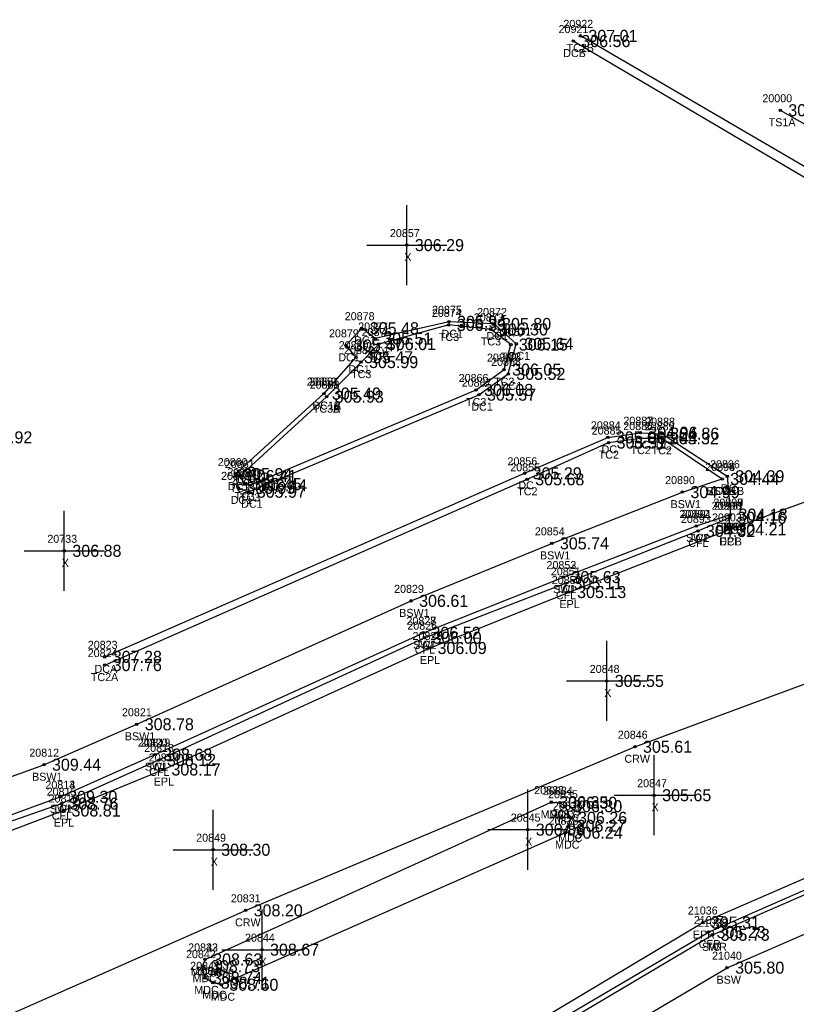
# Model space of a CAD drawing. Extents: x 1970242 to 1971082, y 803104 to 803947.
# Drawn here: x 1970648.9 to 1970745.8, y 803600.7 to 803723.7 of the extents above; entities that cross this region are included whole.
import ezdxf

# ---------------------------------------------------------------- set-up
doc = ezdxf.new("R2010")
doc.units = 0
for name, color, linetype in [('RD_DTM_BkLn1', 7, 'Continuous'), ('RD_DTM_BkLn2', 7, 'Continuous'), ('RD_DTM_BkLn_txCode', 7, 'Continuous'), ('RD_EX_Conc', 7, 'Continuous'), ('RD_EX_Conc_txCode', 7, 'Continuous'), ('RD_EX_Misc', 7, 'Continuous'), ('RD_EX_Misc_txCode', 7, 'Continuous'), ('RD_EX_Road', 7, 'Continuous'), ('RD_EX_Road_txCode', 7, 'Continuous'), ('RD_EX_TX_Conc_ELEV', 7, 'Continuous'), ('RD_EX_TX_Misc_ELEV', 7, 'Continuous'), ('RD_EX_TX_Road_ELEV', 7, 'Continuous'), ('RD_HC_Survey_ELEV', 7, 'Continuous'), ('RD_HC_Survey_txCode', 7, 'Continuous'), ('RD_SMD_Locator', 7, 'Continuous')]:
    doc.layers.add(name, color=color, linetype=linetype)

msp = doc.modelspace()

# ---------------------------------------------------------------- linework, layer by layer
at = {"layer": 'RD_DTM_BkLn1'}
msp.add_lwpolyline([(1970624.03, 803589.05), (1970677.08, 803612.45), (1970725.69, 803632.88), (1970818.37, 803667.22), (1970910.82, 803701.07)], dxfattribs=at)
at = {"layer": 'RD_DTM_BkLn2'}
msp.add_line((1970743.83, 803712.37), (1970787.77, 803687.11), dxfattribs=at)
for points in [[(1970783.35, 803683.84), (1970774.8, 803689.02), (1970772.27, 803690.5), (1970718.87, 803721.66)], [(1970687.2, 803676.6), (1970676.35, 803666.69), (1970676.95, 803665.68), (1970677.62, 803665.53), (1970705.85, 803677.44), (1970709.35, 803679.98), (1970710.19, 803683.11), (1970707.69, 803685), (1970702.44, 803685.56), (1970693.71, 803683.17), (1970691.49, 803680.92), (1970687.2, 803676.6)], [(1970659.49, 803643.08), (1970712.23, 803666.28), (1970722.4, 803670.87), (1970726.37, 803671.43), (1970729.02, 803671.4), (1970736.58, 803666.33)], [(1970618.86, 803619.02), (1970625.27, 803618.4), (1970638.45, 803620.98), (1970653.93, 803626.63), (1970665.79, 803631.9), (1970699.28, 803647.11), (1970716.76, 803654.07), (1970733.36, 803660.46), (1970737.6, 803661.87)], [(1970686.87, 803560.28), (1970689.49, 803570.5), (1970697.58, 803583.18), (1970713.81, 803596.63), (1970735.37, 803609.4), (1970825.99, 803648.95), (1970831.2, 803650.84), (1970835.92, 803652.69), (1970844.52, 803655.97), (1970849.28, 803657.82)]]:
    msp.add_lwpolyline(points, dxfattribs=at)
at = {"layer": 'RD_EX_Conc'}
for points in [[(1970785.58, 803677.59), (1970784.92, 803679.12), (1970784.66, 803679.67), (1970782.46, 803683.16), (1970774.37, 803687.95), (1970773.31, 803686.23), (1970770.57, 803687.79), (1970771.42, 803689.5), (1970717.98, 803721.01)], [(1970686.85, 803676.99), (1970675.79, 803666.93), (1970676.16, 803665.21), (1970677.48, 803664.73), (1970706.21, 803676.85), (1970709.87, 803679.45), (1970710.87, 803683.2), (1970708.09, 803685.68), (1970702.48, 803685.95), (1970693.26, 803683.86), (1970691.58, 803685.15), (1970689.61, 803683.01), (1970690.86, 803681.53), (1970686.85, 803676.99)], [(1970659.5, 803644.11), (1970711.91, 803667.03), (1970722.3, 803671.52), (1970726.36, 803672.1), (1970729.08, 803671.98), (1970737.2, 803666.66), (1970737.6, 803661.87), (1970737.45, 803661.48), (1970737.46, 803660.02)], [(1970619.46, 803623.28), (1970625.12, 803622.92), (1970637.31, 803625.37), (1970651.91, 803630.64), (1970663.49, 803635.69), (1970697.74, 803651.1), (1970715.31, 803658.28), (1970731.61, 803664.68), (1970736.58, 803666.33)], [(1970618.86, 803619.02), (1970625.27, 803618.4), (1970638.45, 803620.98), (1970653.93, 803626.63), (1970665.79, 803631.9), (1970699.28, 803647.11), (1970716.76, 803654.07), (1970733.36, 803660.46), (1970737.6, 803661.87)], [(1970618.57, 803618.39), (1970625.17, 803617.79), (1970638.58, 803620.37), (1970654.08, 803625.78), (1970666.26, 803631.23), (1970699.41, 803646.5), (1970717.02, 803653.29), (1970733.54, 803659.83), (1970737.45, 803661.48)], [(1970686.21, 803560.33), (1970689.09, 803570.66), (1970697.16, 803583.69), (1970713.44, 803597.13), (1970734.87, 803609.74), (1970825.69, 803649.6), (1970830.95, 803651.58)], [(1970686.87, 803560.28), (1970689.49, 803570.5), (1970697.58, 803583.18), (1970713.81, 803596.63), (1970735.37, 803609.4), (1970825.99, 803648.95), (1970831.2, 803650.84)], [(1970691.16, 803559.72), (1970693.96, 803569.01), (1970700.53, 803580.02), (1970716.15, 803592.81), (1970737.19, 803605.29), (1970827.17, 803644.49), (1970832.63, 803646.72), (1970831.2, 803650.84)], [(1970672.03, 803606.32), (1970715.23, 803625.96), (1970716.33, 803625.89), (1970716.96, 803625.45), (1970717.58, 803624.01), (1970717.4, 803623.01), (1970717.02, 803622.15), (1970674.04, 803603.16), (1970672.98, 803603.41), (1970672, 803604.02), (1970671.76, 803605.48), (1970672.03, 803606.32)]]:
    msp.add_lwpolyline(points, dxfattribs=at)
at = {"layer": 'RD_EX_Misc'}
for p, q in [((1970697.21, 803690.53), (1970697.21, 803700.53)), ((1970692.21, 803695.53), (1970702.21, 803695.53)), ((1970654.45, 803652.35), (1970654.45, 803662.35)), ((1970649.45, 803657.35), (1970659.45, 803657.35)), ((1970722.16, 803636.1), (1970722.16, 803646.1)), ((1970717.16, 803641.1), (1970727.16, 803641.1)), ((1970728.08, 803621.83), (1970728.08, 803631.83)), ((1970712.3, 803617.53), (1970712.3, 803627.53)), ((1970723.08, 803626.83), (1970733.08, 803626.83)), ((1970673.03, 803615.02), (1970673.03, 803625.02)), ((1970707.3, 803622.53), (1970717.3, 803622.53)), ((1970668.03, 803620.02), (1970678.03, 803620.02)), ((1970679.13, 803602.54), (1970679.13, 803612.54)), ((1970674.13, 803607.54), (1970684.13, 803607.54))]:
    msp.add_line(p, q, dxfattribs=at)
at = {"layer": 'RD_EX_Road'}
for points in [[(1970591.95, 803626.63), (1970595.64, 803624.22), (1970603.94, 803620.23), (1970610.89, 803618.12), (1970618.56, 803616.95), (1970618.56, 803616.95), (1970625.29, 803616.42), (1970639.01, 803619.1), (1970654.35, 803624.92), (1970666.82, 803630.04), (1970700.04, 803645.21), (1970717.46, 803652.2), (1970737.46, 803660.02), (1970785.58, 803677.59), (1970806.16, 803685.61), (1970810.51, 803687.07), (1970832.41, 803695.41), (1970845.91, 803700.39), (1970902.88, 803721.47)], [(1970707.08, 803502.25), (1970704.83, 803505.7), (1970695.33, 803521.24), (1970688.51, 803536.11), (1970684.99, 803546.09), (1970684.43, 803549.97), (1970685, 803560.52), (1970685, 803560.52), (1970687.77, 803571.3), (1970696.05, 803584.62), (1970712.98, 803598.27), (1970734.15, 803610.93), (1970825.09, 803650.42), (1970830.48, 803652.5), (1970835.31, 803654.39), (1970843.69, 803657.88), (1970848.64, 803660), (1970849.95, 803660.12), (1970917.12, 803684.38)]]:
    msp.add_lwpolyline(points, dxfattribs=at)
at = {"layer": 'RD_SMD_Locator'}
for centre in [(1970717.98, 803721.01), (1970718.87, 803721.66), (1970743.83, 803712.37), (1970697.21, 803695.53), (1970691.58, 803685.15), (1970702.44, 803685.56), (1970702.48, 803685.95), (1970707.69, 803685), (1970708.09, 803685.68), (1970693.26, 803683.86), (1970689.61, 803683.01), (1970693.71, 803683.17), (1970710.19, 803683.11), (1970710.87, 803683.2), (1970690.86, 803681.53), (1970691.49, 803680.92), (1970709.35, 803679.98), (1970709.87, 803679.45), (1970705.85, 803677.44), (1970686.85, 803676.99), (1970686.85, 803676.99), (1970687.2, 803676.6), (1970687.2, 803676.6), (1970706.21, 803676.85), (1970722.3, 803671.52), (1970726.36, 803672.1), (1970726.37, 803671.43), (1970729.02, 803671.4), (1970729.08, 803671.98), (1970722.4, 803670.87), (1970675.79, 803666.93), (1970676.35, 803666.69), (1970711.91, 803667.03), (1970737.2, 803666.66), (1970676.16, 803665.21), (1970676.95, 803665.68), (1970677.62, 803665.53), (1970712.23, 803666.28), (1970736.58, 803666.33), (1970736.58, 803666.33), (1970677.48, 803664.73), (1970731.61, 803664.68), (1970737.45, 803661.48), (1970737.45, 803661.48), (1970737.6, 803661.87), (1970737.6, 803661.87), (1970737.6, 803661.87), (1970733.36, 803660.46), (1970733.36, 803660.46), (1970733.54, 803659.83), (1970737.46, 803660.02), (1970737.46, 803660.02), (1970715.31, 803658.28), (1970654.45, 803657.35), (1970716.76, 803654.07), (1970716.76, 803654.07), (1970717.02, 803653.29), (1970717.46, 803652.2), (1970697.74, 803651.1), (1970699.28, 803647.11), (1970699.28, 803647.11), (1970699.41, 803646.5), (1970700.04, 803645.21), (1970659.49, 803643.08), (1970659.5, 803644.11), (1970722.16, 803641.1), (1970663.49, 803635.69), (1970725.69, 803632.88), (1970665.79, 803631.9), (1970665.79, 803631.9), (1970666.26, 803631.23), (1970651.91, 803630.64), (1970666.82, 803630.04), (1970653.93, 803626.63), (1970653.93, 803626.63), (1970654.08, 803625.78), (1970715.23, 803625.96), (1970716.33, 803625.89), (1970728.08, 803626.83), (1970654.35, 803624.92), (1970716.96, 803625.45), (1970717.58, 803624.01), (1970712.3, 803622.53), (1970717.02, 803622.15), (1970717.4, 803623.01), (1970673.03, 803620.02), (1970677.08, 803612.45), (1970734.15, 803610.93), (1970734.87, 803609.74), (1970735.37, 803609.4), (1970735.37, 803609.4), (1970679.13, 803607.54), (1970672.03, 803606.32), (1970672.03, 803606.32), (1970671.76, 803605.48), (1970737.19, 803605.29), (1970672, 803604.02), (1970672.98, 803603.41), (1970674.04, 803603.16)]:
    msp.add_circle(centre, 0.15, dxfattribs=at)

# ---------------------------------------------------------------- texts
at = {"layer": 'RD_DTM_BkLn_txCode'}
for s, p in [('20000', (1970741.59, 803713.37)), ('TS1A', (1970742.38, 803710.37))]:
    msp.add_text(s, height=1, dxfattribs=at).set_placement(p)
at = {"layer": 'RD_EX_Conc_txCode'}
for s, p in [('20922', (1970716.75, 803722.66)), ('20921', (1970716.15, 803722.01)), ('TC2B', (1970717.15, 803719.66)), ('DCB', (1970716.73, 803719.01)), ('20874', (1970700.33, 803686.56)), ('20875', (1970700.36, 803686.95)), ('20872', (1970705.98, 803686.68)), ('20878', (1970689.46, 803686.15)), ('20873', (1970705.57, 803686)), ('20879', (1970687.49, 803684.01)), ('20877', (1970691.14, 803684.86)), ('20876', (1970691.57, 803684.17)), ('DC1', (1970701.54, 803683.95)), ('20870', (1970708.03, 803684.11)), ('20871', (1970709.03, 803684.2)), ('DC1', (1970690.63, 803683.15)), ('TC3', (1970701.2, 803683.56)), ('TC3', (1970706.44, 803683)), ('DC1', (1970707.15, 803683.68)), ('20880', (1970688.7, 803682.53)), ('20882', (1970689.37, 803681.92)), ('DC1', (1970692.32, 803681.86)), ('DC1', (1970688.66, 803681.01)), ('TC3', (1970692.47, 803681.17)), ('20869', (1970707.21, 803680.98)), ('20868', (1970707.73, 803680.45)), ('TC3', (1970708.94, 803681.11)), ('DC1', (1970709.92, 803681.2)), ('DC1', (1970689.91, 803679.53)), ('20859', (1970684.73, 803677.99)), ('20881', (1970685.02, 803677.99)), ('TC3', (1970690.25, 803678.92)), ('20866', (1970703.68, 803678.44)), ('20867', (1970704.06, 803677.85)), ('TC3', (1970708.11, 803677.98)), ('20858', (1970685.08, 803677.6)), ('20883', (1970685.08, 803677.6)), ('DC1', (1970708.93, 803677.45)), ('TC3', (1970704.6, 803675.44)), ('TC3A', (1970685.47, 803674.6)), ('TC3B', (1970685.48, 803674.6)), ('DC1A', (1970685.42, 803674.99)), ('DC1B', (1970685.43, 803674.99)), ('DC1', (1970705.26, 803674.85)), ('20887', (1970724.24, 803673.1)), ('20888', (1970726.96, 803672.98)), ('20884', (1970720.18, 803672.52)), ('20885', (1970720.29, 803671.87)), ('20886', (1970724.23, 803672.43)), ('20889', (1970726.9, 803672.4)), ('DC', (1970721.52, 803669.52)), ('TC2', (1970725.13, 803669.43)), ('DC', (1970725.58, 803670.1)), ('TC2', (1970727.77, 803669.4)), ('DC', (1970728.3, 803669.98)), ('20856', (1970709.77, 803668.03)), ('TC2', (1970721.16, 803668.87)), ('20860', (1970673.61, 803667.93)), ('20861', (1970674.49, 803667.69)), ('20855', (1970710.12, 803667.28)), ('20894', (1970734.46, 803667.33)), ('20895', (1970734.46, 803667.33)), ('20896', (1970735.06, 803667.66)), ('20863', (1970674.02, 803666.21)), ('20862', (1970674.81, 803666.68)), ('20864', (1970675.34, 803665.73)), ('20865', (1970675.47, 803666.53)), ('20890', (1970729.45, 803665.68)), ('DC1', (1970674.85, 803664.93)), ('TC3', (1970675.11, 803664.69)), ('TC2', (1970710.99, 803664.28)), ('DC', (1970711.13, 803665.03)), ('BSW1B', (1970734.63, 803664.33)), ('TC2B', (1970734.86, 803664.33)), ('DC', (1970736.42, 803664.66)), ('DC1', (1970675.22, 803663.21)), ('TC3', (1970675.7, 803663.68)), ('TC3', (1970676.37, 803663.53)), ('DC1', (1970676.53, 803662.73)), ('BSW1', (1970730.13, 803662.68)), ('20900', (1970735.26, 803662.48)), ('20897', (1970735.48, 803662.87)), ('20898', (1970735.48, 803662.87)), ('20899', (1970735.48, 803662.87)), ('20901', (1970735.58, 803662.48)), ('20892', (1970731.24, 803661.46)), ('20893', (1970731.42, 803660.83)), ('20891', (1970731.53, 803661.46)), ('20903', (1970735.3, 803661.02)), ('CFLB', (1970735.78, 803659.48)), ('SWLB', (1970735.84, 803659.87)), ('TC1B', (1970736.17, 803659.87)), ('DC', (1970736.67, 803659.48)), ('DC', (1970736.82, 803659.87)), ('20854', (1970713.19, 803659.28)), ('SWL', (1970732.07, 803658.46)), ('TC1', (1970732.4, 803658.46)), ('CFL', (1970732.34, 803657.83)), ('DCB', (1970736.21, 803658.02)), ('BSW1', (1970713.83, 803656.28)), ('20852', (1970714.64, 803655.07)), ('20853', (1970714.64, 803655.07)), ('20851', (1970715.19, 803654.29)), ('20829', (1970695.62, 803652.1)), ('SWL', (1970715.47, 803652.07)), ('TC1', (1970715.8, 803652.07)), ('CFL', (1970715.82, 803651.29)), ('BSW1', (1970696.26, 803649.1)), ('20827', (1970697.16, 803648.11)), ('20828', (1970697.16, 803648.11)), ('20826', (1970697.27, 803647.5)), ('20823', (1970657.38, 803645.11)), ('SWL', (1970697.99, 803645.11)), ('TC1', (1970698.32, 803645.11)), ('20824', (1970657.37, 803644.08)), ('CFL', (1970698.2, 803644.5)), ('TC2A', (1970657.76, 803641.08)), ('DCA', (1970658.23, 803642.11)), ('20821', (1970661.65, 803636.69)), ('BSW1', (1970662.01, 803633.69)), ('20820', (1970663.63, 803632.9)), ('20819', (1970663.96, 803632.9)), ('20812', (1970650.08, 803631.64)), ('20818', (1970664.42, 803632.23)), ('SWL', (1970664.5, 803629.9)), ('TC1', (1970664.83, 803629.9)), ('BSW1', (1970650.43, 803628.64)), ('CFL', (1970665.05, 803629.23)), ('20813', (1970652.09, 803627.63)), ('20814', (1970652.09, 803627.63)), ('20815', (1970652.25, 803626.78)), ('20833', (1970713.11, 803626.96)), ('20834', (1970714.21, 803626.89)), ('20835', (1970714.84, 803626.45)), ('20836', (1970715.44, 803625.01)), ('SWL', (1970652.64, 803624.63)), ('CFL', (1970652.88, 803623.78)), ('TC1', (1970652.97, 803624.63)), ('MDC', (1970713.91, 803623.96)), ('MDC', (1970715.01, 803623.89)), ('20837', (1970715.29, 803624.01)), ('20838', (1970714.9, 803623.15)), ('MDC', (1970715.65, 803623.45)), ('MDC', (1970716.26, 803622.01)), ('MDC', (1970715.71, 803620.15)), ('MDC', (1970716.09, 803621.01)), ('21037', (1970733.04, 803610.74)), ('21038', (1970733.53, 803610.4)), ('21039', (1970733.53, 803610.4)), ('CFR', (1970733.64, 803607.74)), ('20842', (1970669.64, 803606.48)), ('20832', (1970669.91, 803607.32)), ('20843', (1970669.91, 803607.32)), ('SWR', (1970734.05, 803607.4)), ('TC', (1970734.57, 803607.4)), ('21040', (1970735.31, 803606.29)), ('20841', (1970670.16, 803605.02)), ('MDCA', (1970670.23, 803604.32)), ('MDCB', (1970670.24, 803604.32)), ('20840', (1970670.82, 803604.41)), ('20839', (1970671.93, 803604.16)), ('MDC', (1970670.45, 803603.48)), ('BSW', (1970735.87, 803603.29)), ('MDC', (1970670.68, 803602.02)), ('MDC', (1970671.67, 803601.41)), ('MDC', (1970672.73, 803601.16))]:
    msp.add_text(s, height=1, dxfattribs=at).set_placement(p)
at = {"layer": 'RD_EX_Misc_txCode'}
for s, p in [('20857', (1970695.1, 803696.53)), ('X', (1970696.9, 803693.53)), ('20733', (1970652.33, 803658.35)), ('X', (1970654.13, 803655.35)), ('20848', (1970720.04, 803642.1)), ('X', (1970721.85, 803639.1)), ('20847', (1970725.96, 803627.83)), ('X', (1970727.76, 803624.83)), ('20845', (1970710.18, 803623.53)), ('20849', (1970670.91, 803621.02)), ('X', (1970711.98, 803620.53)), ('X', (1970672.72, 803618.02)), ('20844', (1970677.01, 803608.54)), ('X', (1970678.82, 803605.54))]:
    msp.add_text(s, height=1, dxfattribs=at).set_placement(p)
at = {"layer": 'RD_EX_Road_txCode'}
for s, p in [('20902', (1970735.3, 803661.02)), ('EPL', (1970736.26, 803658.02)), ('20850', (1970715.3, 803653.2)), ('EPL', (1970716.26, 803650.2)), ('20825', (1970697.92, 803646.21)), ('EPL', (1970698.84, 803643.21)), ('20817', (1970664.99, 803631.04)), ('EPL', (1970665.62, 803628.04)), ('20816', (1970652.49, 803625.92)), ('EPL', (1970653.14, 803622.92)), ('21036', (1970732.29, 803611.93)), ('EPR', (1970732.92, 803608.93))]:
    msp.add_text(s, height=1, dxfattribs=at).set_placement(p)
at = {"layer": 'RD_EX_TX_Conc_ELEV'}
for s, p in [('307.01', (1970719.87, 803720.91)), ('306.56', (1970718.98, 803720.26)), ('306.39', (1970703.44, 803684.81)), ('305.94', (1970703.48, 803685.2)), ('305.80', (1970709.09, 803684.93)), ('305.48', (1970692.58, 803684.4)), ('306.30', (1970708.69, 803684.25)), ('305.47', (1970690.61, 803682.26)), ('305.51', (1970694.26, 803683.11)), ('306.01', (1970694.71, 803682.42)), ('306.15', (1970711.19, 803682.36)), ('305.64', (1970711.87, 803682.45)), ('305.47', (1970691.86, 803680.78)), ('305.99', (1970692.49, 803680.17)), ('306.05', (1970710.35, 803679.23)), ('305.52', (1970710.87, 803678.7)), ('305.49', (1970687.85, 803676.24)), ('305.49', (1970687.85, 803676.24)), ('306.08', (1970706.85, 803676.69)), ('305.57', (1970707.21, 803676.1)), ('305.93', (1970688.2, 803675.85)), ('305.93', (1970688.2, 803675.85)), ('304.96', (1970727.36, 803671.35)), ('304.86', (1970730.08, 803671.23)), ('305.06', (1970723.3, 803670.77)), ('305.51', (1970723.4, 803670.12)), ('305.44', (1970727.37, 803670.68)), ('305.32', (1970730.02, 803670.65)), ('305.29', (1970712.91, 803666.28)), ('305.94', (1970676.79, 803666.18)), ('306.41', (1970677.35, 803665.94)), ('305.68', (1970713.23, 803665.53)), ('304.44', (1970737.58, 803665.58)), ('304.44', (1970737.58, 803665.58)), ('304.39', (1970738.2, 803665.91)), ('305.99', (1970677.16, 803664.46)), ('306.45', (1970677.95, 803664.93)), ('305.97', (1970678.48, 803663.98)), ('306.44', (1970678.62, 803664.78)), ('304.99', (1970732.61, 803663.93)), ('304.16', (1970738.45, 803660.73)), ('304.16', (1970738.45, 803660.73)), ('304.18', (1970738.6, 803661.12)), ('304.18', (1970738.6, 803661.12)), ('304.18', (1970738.6, 803661.12)), ('304.83', (1970734.36, 803659.71)), ('304.83', (1970734.36, 803659.71)), ('304.32', (1970734.54, 803659.08)), ('304.21', (1970738.46, 803659.27)), ('305.74', (1970716.31, 803657.53)), ('305.63', (1970717.76, 803653.32)), ('305.63', (1970717.76, 803653.32)), ('305.11', (1970718.02, 803652.54)), ('306.61', (1970698.74, 803650.35)), ('306.52', (1970700.28, 803646.36)), ('306.52', (1970700.28, 803646.36)), ('306.00', (1970700.41, 803645.75)), ('307.28', (1970660.5, 803643.36)), ('307.76', (1970660.49, 803642.33)), ('308.78', (1970664.49, 803634.94)), ('308.68', (1970666.79, 803631.15)), ('308.68', (1970666.79, 803631.15)), ('309.44', (1970652.91, 803629.89)), ('308.12', (1970667.26, 803630.48)), ('309.30', (1970654.93, 803625.88)), ('309.30', (1970654.93, 803625.88)), ('308.76', (1970655.08, 803625.03)), ('306.35', (1970716.23, 803625.21)), ('306.30', (1970717.33, 803625.14)), ('306.30', (1970717.96, 803624.7)), ('306.26', (1970718.58, 803623.26)), ('306.27', (1970718.4, 803622.26)), ('306.24', (1970718.02, 803621.4)), ('305.23', (1970735.87, 803608.99)), ('305.73', (1970736.37, 803608.65)), ('305.73', (1970736.37, 803608.65)), ('308.73', (1970672.76, 803604.73)), ('308.63', (1970673.03, 803605.57)), ('308.63', (1970673.03, 803605.57)), ('305.80', (1970738.19, 803604.54)), ('308.74', (1970673, 803603.27)), ('308.71', (1970673.98, 803602.66)), ('308.60', (1970675.04, 803602.41))]:
    msp.add_text(s, height=1.5, dxfattribs=at).set_placement(p)
at = {"layer": 'RD_EX_TX_Misc_ELEV'}
for s, p in [('305.00', (1970744.83, 803711.62)), ('306.29', (1970698.21, 803694.78)), ('307.92', (1970644.32, 803670.77)), ('306.88', (1970655.45, 803656.6)), ('305.55', (1970723.16, 803640.35)), ('305.65', (1970729.08, 803626.08)), ('306.86', (1970713.3, 803621.78)), ('308.30', (1970674.03, 803619.27)), ('308.67', (1970680.13, 803606.79))]:
    msp.add_text(s, height=1.5, dxfattribs=at).set_placement(p)
at = {"layer": 'RD_EX_TX_Road_ELEV'}
for s, p in [('304.21', (1970738.46, 803659.27)), ('305.13', (1970718.46, 803651.45)), ('306.09', (1970701.04, 803644.46)), ('308.17', (1970667.82, 803629.29)), ('308.81', (1970655.35, 803624.17)), ('305.31', (1970735.15, 803610.18))]:
    msp.add_text(s, height=1.5, dxfattribs=at).set_placement(p)
at = {"layer": 'RD_HC_Survey_ELEV'}
for s, p in [('305.61', (1970726.69, 803632.13)), ('308.20', (1970678.08, 803611.7))]:
    msp.add_text(s, height=1.5, dxfattribs=at).set_placement(p)
at = {"layer": 'RD_HC_Survey_txCode'}
for s, p in [('20846', (1970723.55, 803633.88)), ('CRW', (1970724.37, 803630.88)), ('20831', (1970675.24, 803613.45)), ('CRW', (1970675.76, 803610.45))]:
    msp.add_text(s, height=1, dxfattribs=at).set_placement(p)

doc.saveas('drawing.dxf')
